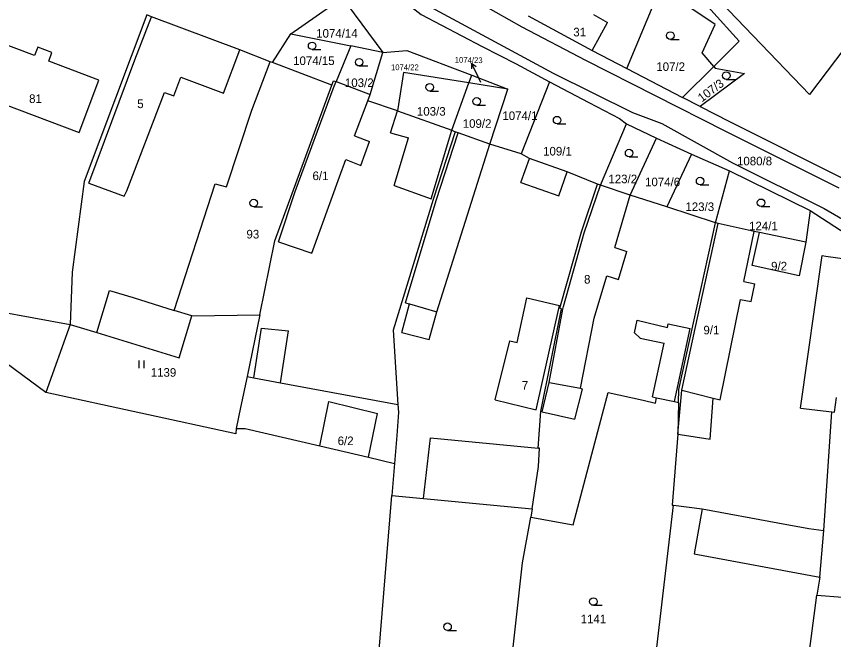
# Model space of a CAD drawing. Extents: x -746176 to -739709, y -1128407 to -1124482.
# Drawn here: x -742377 to -742215.1, y -1126240.2 to -1126116.8 of the extents above; entities that cross this region are included whole.
import ezdxf

# ---------------------------------------------------------------- set-up
doc = ezdxf.new("R2010")
doc.units = 0
for name, color, linetype in [('Vrstva 33', 7, 'Continuous'), ('Vrstva 42', 7, 'Continuous'), ('Vrstva 43', 7, 'Continuous'), ('Vrstva 44', 7, 'Continuous'), ('Vrstva 47', 7, 'Continuous')]:
    doc.layers.add(name, color=color, linetype=linetype)

msp = doc.modelspace()

# ---------------------------------------------------------------- linework, layer by layer
at = {"layer": 'Vrstva 33'}
for p, q in [((-742256.06, -1126127.14), (-742249.36, -1126111.09)), ((-742326.25, -1126125.97), (-742322.59, -1126120.3)), ((-742322.59, -1126120.3), (-742310.73, -1126122.68)), ((-742310.73, -1126122.68), (-742313.65, -1126129.74)), ((-742304.4, -1126124.01), (-742310.73, -1126122.68)), ((-742233.84, -1126121.75), (-742238.85, -1126126.73)), ((-742306.9, -1126132.3), (-742304.4, -1126124.01)), ((-742238.85, -1126126.73), (-742241.16, -1126124.04)), ((-742326.25, -1126125.97), (-742326.7, -1126125.8)), ((-742314.45, -1126130.46), (-742326.25, -1126125.97)), ((-742256.06, -1126127.14), (-742245.01, -1126132.86)), ((-742245.01, -1126132.86), (-742238.85, -1126126.73)), ((-742238.85, -1126126.73), (-742238.56, -1126127.06)), ((-742300.31, -1126127.94), (-742301.49, -1126135.55)), ((-742287.33, -1126129.99), (-742300.31, -1126127.94)), ((-742287.33, -1126129.99), (-742286.78, -1126128.49)), ((-742286.78, -1126128.49), (-742279.63, -1126131.21)), ((-742313.65, -1126129.74), (-742306.9, -1126132.3)), ((-742290.74, -1126139.38), (-742287.33, -1126129.99)), ((-742279.63, -1126131.21), (-742287.33, -1126129.99)), ((-742271.38, -1126129.77), (-742276.96, -1126144.02)), ((-742283.2, -1126142.1), (-742279.63, -1126131.21)), ((-742241.52, -1126134.66), (-742245.01, -1126132.86)), ((-742301.49, -1126135.55), (-742290.74, -1126139.38)), ((-742261.26, -1126150.24), (-742256.1, -1126138.11)), ((-742256.1, -1126138.11), (-742250.15, -1126140.92)), ((-742290.74, -1126139.38), (-742290.03, -1126139.66)), ((-742276.96, -1126144.02), (-742283.2, -1126142.1)), ((-742255.42, -1126152.21), (-742250.15, -1126140.92)), ((-742250.15, -1126140.92), (-742243.28, -1126144.09)), ((-742243.28, -1126144.09), (-742248.16, -1126154.55)), ((-742243.28, -1126144.09), (-742235.72, -1126147.41)), ((-742238.52, -1126157.67), (-742235.72, -1126147.41)), ((-742235.72, -1126147.41), (-742219.77, -1126155.24)), ((-742261.26, -1126150.24), (-742261.84, -1126150.05)), ((-742255.42, -1126152.21), (-742261.26, -1126150.24)), ((-742248.16, -1126154.55), (-742255.42, -1126152.21)), ((-742238.52, -1126157.67), (-742248.16, -1126154.55)), ((-742219.77, -1126155.24), (-742220.62, -1126161.55)), ((-742219.77, -1126155.24), (-742210.43, -1126161.29)), ((-742220.62, -1126161.55), (-742229.8, -1126159.63)), ((-742408.55, -1126170.19), (-742366.28, -1126177.8)), ((-742342.18, -1126176.09), (-742328.77, -1126175.93)), ((-742328.77, -1126175.93), (-742331.28, -1126188.11)), ((-742366.28, -1126177.8), (-742371.13, -1126191.3)), ((-742331.28, -1126188.11), (-742332.55, -1126194.28)), ((-742332.55, -1126194.28), (-742333.4, -1126198.44)), ((-742302.07, -1126205.33), (-742302.59, -1126211.7)), ((-742274.79, -1126214.34), (-742275.09, -1126215.95)), ((-742253.45, -1126270.36), (-742246.8, -1126213.59)), ((-742217.86, -1126227.84), (-742218.41, -1126231.43)), ((-742226.78, -1126295.24), (-742218.41, -1126231.43)), ((-742218.41, -1126231.43), (-742213.31, -1126231.82))]:
    msp.add_line(p, q, dxfattribs=at)
for points in [[(-742322.88, -1126080.92), (-742314.75, -1126099.48), (-742306.74, -1126108.67), (-742296.81, -1126116.44), (-742284.71, -1126122.79), (-742278, -1126126.23), (-742271.38, -1126129.77)], [(-742226.91, -1126088.92), (-742220.21, -1126088.74), (-742209.67, -1126089.51), (-742205.42, -1126090.21), (-742203.87, -1126091.46), (-742201.62, -1126095.17), (-742208.44, -1126114.62), (-742212.86, -1126123.04), (-742219.9, -1126132.27), (-742250.27, -1126100.63), (-742249.53, -1126099.74), (-742247.13, -1126097.23), (-742241.64, -1126096.04), (-742237.53, -1126090.17), (-742226.91, -1126088.92)], [(-742253.64, -1126102.41), (-742239.39, -1126115.53), (-742233.84, -1126121.75)], [(-742241.16, -1126124.04), (-742238.58, -1126118.41), (-742249.36, -1126111.09)], [(-742322.59, -1126120.3), (-742314.77, -1126114.82), (-742311.38, -1126114.53), (-742304.4, -1126124.01)], [(-742351.14, -1126116.55), (-742363.54, -1126149.51), (-742365.92, -1126167.47), (-742366.28, -1126177.8)], [(-742326.7, -1126125.8), (-742332.7, -1126123.44), (-742350.2, -1126116.9), (-742351.14, -1126116.55)], [(-742275.57, -1126116.75), (-742262.95, -1126123.57), (-742256.06, -1126127.14)], [(-742360.61, -1126129.44), (-742370.56, -1126125.67), (-742369.93, -1126124), (-742372.74, -1126122.95), (-742373.37, -1126124.6), (-742381.46, -1126121.54), (-742385.41, -1126131.94), (-742364.54, -1126139.8), (-742360.61, -1126129.44)], [(-742304.4, -1126124.01), (-742299.64, -1126123.59), (-742286.78, -1126128.49)], [(-742342.18, -1126176.09), (-742345.69, -1126175.02), (-742337.62, -1126150), (-742335.33, -1126150.55), (-742330.35, -1126135.4), (-742326.7, -1126125.8)], [(-742238.56, -1126127.06), (-742232.76, -1126128.14), (-742241.52, -1126134.66)], [(-742328.77, -1126175.93), (-742325.75, -1126161.24), (-742314.45, -1126130.46)], [(-742314.45, -1126130.46), (-742314.12, -1126129.57), (-742313.65, -1126129.74)], [(-742271.38, -1126129.77), (-742263.55, -1126133.89), (-742257.51, -1126137.07), (-742256.1, -1126138.11)], [(-742301.49, -1126135.55), (-742307.36, -1126133.52), (-742306.9, -1126132.3)], [(-742241.52, -1126134.66), (-742235.74, -1126137.65), (-742212.93, -1126149.05), (-742177.34, -1126171.16)], [(-742290.03, -1126139.66), (-742294.39, -1126153.07), (-742302.36, -1126178.95), (-742301.38, -1126193.67)], [(-742283.2, -1126142.1), (-742289.47, -1126139.88), (-742290.03, -1126139.66)], [(-742261.84, -1126150.05), (-742267.85, -1126147.6), (-742275.32, -1126144.93), (-742276.96, -1126144.02)], [(-742274.79, -1126214.34), (-742273.54, -1126205.94), (-742273.34, -1126202.32), (-742273.6, -1126202.3), (-742273.12, -1126195.05), (-742269.02, -1126174.69), (-742269.3, -1126174.61), (-742265.06, -1126159.49), (-742261.84, -1126150.05)], [(-742245.81, -1126193.24), (-742245.74, -1126190.69), (-742238.52, -1126157.67)], [(-742229.8, -1126159.63), (-742230.81, -1126159.4), (-742237.95, -1126157.86), (-742238.52, -1126157.67)], [(-742220.62, -1126161.55), (-742221.93, -1126168.17), (-742231.21, -1126166.16), (-742229.8, -1126159.63)], [(-742366.28, -1126177.8), (-742361.05, -1126179.41), (-742344.7, -1126184.42), (-742342.18, -1126176.09)], [(-742371.13, -1126191.3), (-742382.1, -1126183.23), (-742395.78, -1126181.85), (-742403.65, -1126182.31), (-742424.12, -1126188.09), (-742455.22, -1126201.03)], [(-742331.28, -1126188.11), (-742329.94, -1126188.36), (-742324.62, -1126189.35), (-742301.38, -1126193.67)], [(-742333.4, -1126198.44), (-742333.49, -1126199.45), (-742371.13, -1126191.3)], [(-742275.09, -1126215.95), (-742266.66, -1126217.47), (-742260.87, -1126195.48), (-742259.76, -1126191.3), (-742252.85, -1126192.83), (-742250.39, -1126193.38), (-742250.2, -1126192.33), (-742246.63, -1126193.07), (-742245.81, -1126193.24)], [(-742217.86, -1126227.84), (-742217.03, -1126218.63), (-742215.44, -1126195.1), (-742214.95, -1126195.15), (-742214.53, -1126192.26)], [(-742301.38, -1126193.67), (-742301.28, -1126195.16), (-742301.61, -1126199.8), (-742302.07, -1126205.33)], [(-742245.81, -1126193.24), (-742245.98, -1126199.54), (-742247.06, -1126213.57), (-742246.8, -1126213.59)], [(-742333.4, -1126198.44), (-742331.66, -1126198.39), (-742316.87, -1126201.82), (-742307.21, -1126204.11), (-742302.07, -1126205.33)], [(-742281.72, -1126273.18), (-742307.41, -1126266.17), (-742306.81, -1126260.62), (-742305.51, -1126247.12), (-742302.59, -1126211.7)], [(-742302.59, -1126211.7), (-742296.36, -1126212.29), (-742274.79, -1126214.34)], [(-742246.8, -1126213.59), (-742241.16, -1126214.28), (-742242.7, -1126223.21), (-742217.86, -1126227.84)], [(-742281.72, -1126273.18), (-742280.8, -1126262.02), (-742276.72, -1126225.02), (-742275.09, -1126215.95)]]:
    msp.add_lwpolyline(points, dxfattribs=at)
at = {"layer": 'Vrstva 43'}
for p, q in [((-742286.81, -1126126.09), (-742286.82, -1126127.21)), ((-742285.49, -1126128.79), (-742286.81, -1126126.09)), ((-742286.81, -1126126.09), (-742285.92, -1126126.77)), ((-742284.96, -1126129.91), (-742285.49, -1126128.79))]:
    msp.add_line(p, q, dxfattribs=at)
at = {"layer": 'Vrstva 44'}
for p, q in [((-742247.44, -1126121.38), (-742245.69, -1126121.38)), ((-742318.38, -1126123.41), (-742316.63, -1126123.41)), ((-742309.07, -1126126.65), (-742307.32, -1126126.65)), ((-742236.37, -1126129.31), (-742234.62, -1126129.31)), ((-742295.09, -1126131.61), (-742293.34, -1126131.61)), ((-742285.78, -1126134.42), (-742284.03, -1126134.42)), ((-742269.86, -1126138.12), (-742268.11, -1126138.12)), ((-742255.6, -1126144.64), (-742253.85, -1126144.64)), ((-742241.54, -1126150.17), (-742239.79, -1126150.17)), ((-742329.94, -1126154.54), (-742328.19, -1126154.54)), ((-742229.47, -1126154.48), (-742227.72, -1126154.48)), ((-742352.65, -1126186.46), (-742352.65, -1126184.96)), ((-742351.65, -1126186.46), (-742351.65, -1126184.96)), ((-742262.68, -1126233.41), (-742260.93, -1126233.41)), ((-742291.57, -1126238.39), (-742289.82, -1126238.39))]:
    msp.add_line(p, q, dxfattribs=at)
for centre in [(-742247.44, -1126120.63), (-742318.38, -1126122.66), (-742309.07, -1126125.9), (-742236.37, -1126128.56), (-742295.09, -1126130.86), (-742285.78, -1126133.67), (-742269.86, -1126137.37), (-742255.6, -1126143.89), (-742241.54, -1126149.42), (-742329.94, -1126153.79), (-742229.47, -1126153.73), (-742262.68, -1126232.66), (-742291.57, -1126237.64)]:
    msp.add_circle(centre, 0.75, dxfattribs=at)
at = {"layer": 'Vrstva 47'}
for p, q in [((-742296.2, -1126107.89), (-742276.88, -1126118.92)), ((-742297.3, -1126113.67), (-742283.82, -1126120.97)), ((-742353.49, -1126125.42), (-742350.2, -1126116.9)), ((-742262.66, -1126116.47), (-742259.87, -1126118.01)), ((-742276.88, -1126118.92), (-742264.25, -1126125.49)), ((-742262.95, -1126123.57), (-742259.87, -1126118.01)), ((-742283.82, -1126120.97), (-742270.64, -1126128.09)), ((-742335.92, -1126132.03), (-742332.7, -1126123.44)), ((-742362.62, -1126149.84), (-742353.49, -1126125.42)), ((-742264.25, -1126125.49), (-742236.63, -1126139.49)), ((-742345.76, -1126132.56), (-742344.4, -1126128.89)), ((-742344.4, -1126128.89), (-742335.92, -1126132.03)), ((-742270.64, -1126128.09), (-742254.96, -1126135.85)), ((-742321.76, -1126151.49), (-742313.99, -1126130.63)), ((-742313.99, -1126130.63), (-742313.65, -1126129.74)), ((-742355.11, -1126151.35), (-742347.65, -1126131.87)), ((-742347.65, -1126131.87), (-742345.76, -1126132.56)), ((-742309.98, -1126140.49), (-742307.36, -1126133.52)), ((-742302.87, -1126139.86), (-742301.49, -1126135.55)), ((-742254.96, -1126135.85), (-742249.1, -1126138.06)), ((-742249.1, -1126138.06), (-742235.14, -1126145.83)), ((-742309.98, -1126140.49), (-742306.99, -1126141.62)), ((-742302.87, -1126139.86), (-742299.31, -1126140.9)), ((-742294.78, -1126152.93), (-742290.74, -1126139.38)), ((-742293.82, -1126153.25), (-742289.47, -1126139.88)), ((-742236.63, -1126139.49), (-742214.05, -1126150.74)), ((-742308.71, -1126146.33), (-742306.99, -1126141.62)), ((-742302.15, -1126150.33), (-742299.31, -1126140.9)), ((-742293.68, -1126175.34), (-742283.2, -1126142.1)), ((-742312.98, -1126148.6), (-742311.68, -1126145.17)), ((-742311.68, -1126145.17), (-742308.71, -1126146.33)), ((-742277.02, -1126149.7), (-742275.32, -1126144.93)), ((-742235.14, -1126145.83), (-742216.99, -1126154.85)), ((-742318.44, -1126163.68), (-742312.98, -1126148.6)), ((-742269.51, -1126152.34), (-742267.85, -1126147.6)), ((-742362.62, -1126149.84), (-742355.61, -1126152.4)), ((-742302.15, -1126150.33), (-742294.78, -1126152.93)), ((-742277.02, -1126149.7), (-742269.51, -1126152.34)), ((-742264.5, -1126159.68), (-742261.26, -1126150.24)), ((-742355.61, -1126152.4), (-742355.11, -1126151.35)), ((-742325.07, -1126161.47), (-742321.76, -1126151.49)), ((-742299.86, -1126173.52), (-742293.82, -1126153.25)), ((-742258.44, -1126162.59), (-742255.42, -1126152.21)), ((-742216.99, -1126154.85), (-742209.7, -1126159.09)), ((-742242.53, -1126178.6), (-742237.95, -1126157.86)), ((-742268.58, -1126174.24), (-742264.5, -1126159.68)), ((-742232.86, -1126169.31), (-742230.81, -1126159.4)), ((-742325.07, -1126161.47), (-742318.44, -1126163.68)), ((-742258.44, -1126162.59), (-742256.05, -1126163.36)), ((-742257.72, -1126168.93), (-742256.05, -1126163.36)), ((-742221.64, -1126194.36), (-742217.39, -1126164.16)), ((-742217.39, -1126164.16), (-742216.66, -1126164.27)), ((-742216.66, -1126164.27), (-742211.41, -1126165.02)), ((-742262.5, -1126176.58), (-742260.05, -1126168.17)), ((-742260.05, -1126168.17), (-742257.72, -1126168.93)), ((-742232.86, -1126169.31), (-742230.73, -1126169.75)), ((-742231.44, -1126173.28), (-742230.73, -1126169.75)), ((-742361.05, -1126179.41), (-742358.51, -1126171.1)), ((-742358.51, -1126171.1), (-742353.86, -1126172.49)), ((-742353.86, -1126172.49), (-742345.69, -1126175.02)), ((-742277.79, -1126181.37), (-742275.84, -1126172.55)), ((-742275.84, -1126172.55), (-742269.42, -1126174.05)), ((-742237.59, -1126192.75), (-742233.53, -1126172.88)), ((-742233.53, -1126172.88), (-742231.44, -1126173.28)), ((-742300.61, -1126179.42), (-742299.11, -1126173.74)), ((-742299.86, -1126173.52), (-742299.11, -1126173.74)), ((-742299.11, -1126173.74), (-742293.68, -1126175.34)), ((-742274.02, -1126194.74), (-742269.42, -1126174.05)), ((-742268.73, -1126174.77), (-742268.58, -1126174.24)), ((-742295.23, -1126180.82), (-742293.68, -1126175.34)), ((-742271.45, -1126189.28), (-742268.73, -1126174.77)), ((-742265.2, -1126190.4), (-742262.5, -1126176.58)), ((-742254.53, -1126179.5), (-742254.01, -1126176.99)), ((-742254.01, -1126176.99), (-742248, -1126178.41)), ((-742248, -1126178.41), (-742247.84, -1126177.67)), ((-742247.84, -1126177.67), (-742243.51, -1126178.62)), ((-742329.94, -1126188.36), (-742328.41, -1126178.52)), ((-742328.41, -1126178.52), (-742323.05, -1126179.05)), ((-742324.62, -1126189.35), (-742323.05, -1126179.05)), ((-742300.61, -1126179.42), (-742295.23, -1126180.82)), ((-742246.63, -1126193.07), (-742243.51, -1126178.62)), ((-742245.16, -1126190.83), (-742242.53, -1126178.6)), ((-742282.11, -1126192.72), (-742279.25, -1126181.03)), ((-742279.25, -1126181.03), (-742277.79, -1126181.37)), ((-742254.53, -1126179.5), (-742253.42, -1126180.51)), ((-742253.42, -1126180.51), (-742248.68, -1126181.54)), ((-742250.98, -1126192.17), (-742248.68, -1126181.54)), ((-742272.83, -1126195.11), (-742271.45, -1126189.28)), ((-742271.45, -1126189.28), (-742265.2, -1126190.4)), ((-742266.38, -1126196.53), (-742264.83, -1126190.6)), ((-742265.2, -1126190.4), (-742264.83, -1126190.6)), ((-742250.98, -1126192.17), (-742250.2, -1126192.33)), ((-742245.98, -1126199.54), (-742245.16, -1126190.83)), ((-742245.16, -1126190.83), (-742238.94, -1126192.41)), ((-742239.56, -1126200.52), (-742238.94, -1126192.41)), ((-742238.94, -1126192.41), (-742237.59, -1126192.75)), ((-742316.87, -1126201.82), (-742315.09, -1126193.06)), ((-742315.09, -1126193.06), (-742305.41, -1126195.41)), ((-742282.11, -1126192.72), (-742274.02, -1126194.74)), ((-742307.21, -1126204.11), (-742305.41, -1126195.41)), ((-742272.83, -1126195.11), (-742266.38, -1126196.53)), ((-742221.64, -1126194.36), (-742215.44, -1126195.1)), ((-742296.36, -1126212.29), (-742294.97, -1126200.25)), ((-742294.97, -1126200.25), (-742273.6, -1126202.3)), ((-742245.98, -1126199.54), (-742245.51, -1126199.61)), ((-742245.51, -1126199.61), (-742239.56, -1126200.52)), ((-742241.16, -1126214.28), (-742226.13, -1126217.11)), ((-742226.13, -1126217.11), (-742220, -1126218.18)), ((-742220, -1126218.18), (-742217.03, -1126218.63))]:
    msp.add_line(p, q, dxfattribs=at)

# ---------------------------------------------------------------- texts
at = {"layer": 'Vrstva 42'}
for s, height, p in [('1074/14', 1.7, (-742317.58, -1126121.04)), ('31', 1.7, (-742266.66, -1126120.79)), ('1074/15', 1.7, (-742322.15, -1126126.46)), ('107/2', 1.7, (-742250.22, -1126127.63)), ('1074/22', 1.139, (-742302.77, -1126127.48)), ('103/2', 1.7, (-742311.89, -1126130.82)), ('81', 1.7, (-742374.44, -1126133.97)), ('5', 1.7, (-742353.02, -1126134.98)), ('103/3', 1.7, (-742297.63, -1126136.48)), ('1074/1', 1.7, (-742280.71, -1126137.35)), ('109/2', 1.7, (-742288.56, -1126138.89)), ('109/1', 1.7, (-742272.64, -1126144.37)), ('1080/8', 1.7, (-742234.24, -1126146.32)), ('6/1', 1.7, (-742318.31, -1126149.24)), ('123/2', 1.7, (-742259.71, -1126149.86)), ('1074/6', 1.7, (-742252.45, -1126150.45)), ('123/3', 1.7, (-742244.45, -1126155.36)), ('124/1', 1.7, (-742231.85, -1126159.17)), ('93', 1.7, (-742331.39, -1126160.79)), ('9/2', 1.7, (-742227.48, -1126167.12)), ('8', 1.7, (-742264.53, -1126169.72)), ('9/1', 1.7, (-742240.89, -1126179.77)), ('1139', 1.7, (-742350.35, -1126188.16)), ('7', 1.7, (-742276.85, -1126190.71)), ('6/2', 1.7, (-742313.33, -1126201.7)), ('1141', 1.7, (-742265.2, -1126236.96))]:
    msp.add_text(s, height=height, dxfattribs=at).set_placement(p)
for s, height, rotation, p in [('1074/23', 1.139, 359, (-742290.14, -1126125.99)), ('107/3', 1.7, 37, (-742241.2, -1126133.88))]:
    msp.add_text(s, height=height, rotation=rotation, dxfattribs=at).set_placement(p)

doc.saveas('drawing.dxf')
